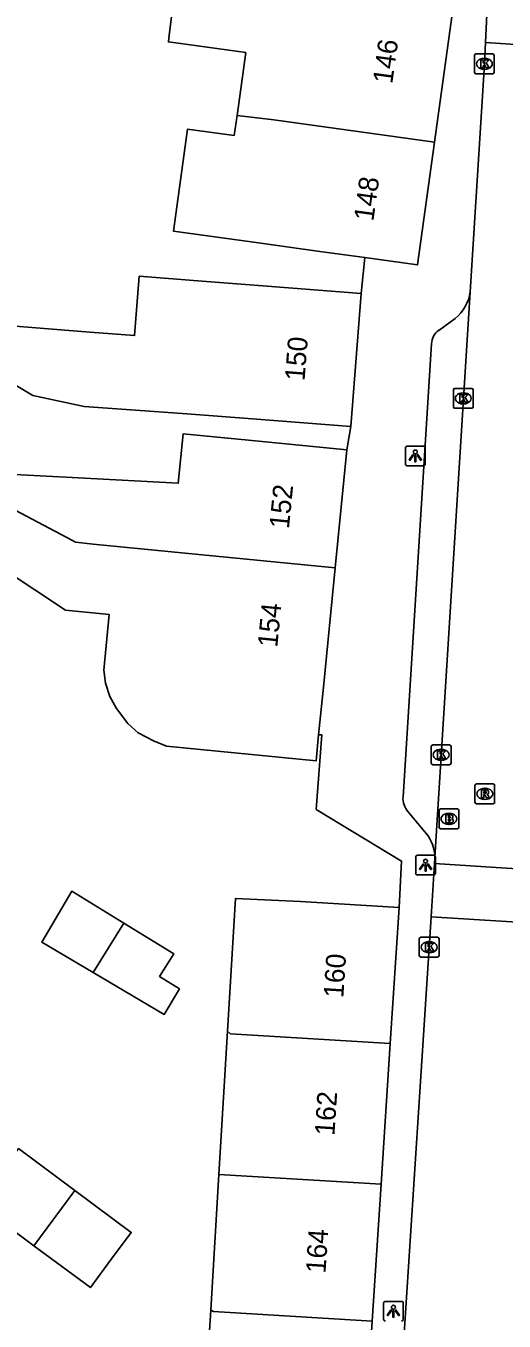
# Model space of a CAD drawing. Extents: x 160107 to 160928, y 382056 to 382918.
# Drawn here: x 160535.6 to 160559.8, y 382517.3 to 382582.9 of the extents above; entities that cross this region are included whole.
import ezdxf

# ---------------------------------------------------------------- set-up
doc = ezdxf.new("R2010")
doc.units = 0
for name, color, linetype in [('IMGEO_Brandkraan', 7, 'Continuous'), ('IMGEO_Kolk', 7, 'Continuous'), ('IMGEO_Lichtpunt', 7, 'Continuous'), ('IMGEO_Pand', 7, 'Continuous'), ('IMGEO_Pand_nummerreeks', 7, 'Continuous'), ('IMGEO_Rijbaan_lokaal_open', 7, 'Continuous'), ('IMGEO_Rioolput', 7, 'Continuous'), ('IMGEO_Voetpad_open', 7, 'Continuous')]:
    doc.layers.add(name, color=color, linetype=linetype)

msp = doc.modelspace()

# ---------------------------------------------------------------- linework, layer by layer
at = {"layer": 'IMGEO_Brandkraan'}
for p, q in [((160556.501, 382542.322), (160556.501, 382543.174)), ((160556.576, 382543.248), (160557.428, 382543.248)), ((160556.989, 382543.028), (160557.014, 382543.028)), ((160557.502, 382543.174), (160557.502, 382542.322)), ((160557.428, 382542.248), (160556.576, 382542.248)), ((160557.012, 382542.468), (160556.987, 382542.468))]:
    msp.add_line(p, q, dxfattribs=at)
for points in [[(160556.501, 382542.322), (160556.501, 382543.174)], [(160556.576, 382543.248), (160557.428, 382543.248)], [(160556.849, 382542.948), (160556.849, 382542.548), (160557.062, 382542.548)], [(160557.08, 382542.948), (160556.849, 382542.948)], [(160557.028, 382542.867), (160556.974, 382542.867), (160556.974, 382542.791)], [(160556.974, 382542.791), (160557.027, 382542.791)], [(160557.502, 382543.174), (160557.502, 382542.322)], [(160557.428, 382542.248), (160556.576, 382542.248)], [(160557.036, 382542.715), (160556.974, 382542.715), (160556.974, 382542.634)], [(160556.974, 382542.634), (160557.036, 382542.634)]]:
    msp.add_lwpolyline(points, dxfattribs=at)
for centre, radius, start, end in [((160556.578, 382543.172), 0.0765, 91.55205, 178.44795), ((160556.578, 382543.172), 0.0765, 91.55205, 178.44795), ((160557.029, 382542.829), 0.0379, 267.82845, 90.93552), ((160557.084, 382542.803), 0.145, 59.4692, 91.53667), ((160557.109, 382542.85), 0.0922, 285.51372, 58.15012), ((160557.114, 382542.658), 0.105, 301.31148, 78.98903), ((160557.426, 382543.172), 0.0765, 1.55205, 88.44795), ((160557.426, 382543.172), 0.0765, 1.55205, 88.44795), ((160556.578, 382542.324), 0.0765, 181.55205, 268.44795), ((160556.578, 382542.324), 0.0765, 181.55205, 268.44795), ((160557.037, 382542.674), 0.0404, 269.87594, 90.50774), ((160557.068, 382542.799), 0.251, 268.66757, 293.53466), ((160557.426, 382542.324), 0.0765, 271.55205, 358.44795), ((160557.426, 382542.324), 0.0765, 271.55205, 358.44795)]:
    msp.add_arc(centre, radius, start, end, dxfattribs=at)
for centre, major_axis, ratio, start_param, end_param in [((160556.988, 382542.748), (-0.387, 0.002), 0.722429, 4.712389, 7.853982), ((160557.013, 382542.748), (-0.39, 0.002), 0.717154, 1.570796, 4.712389)]:
    msp.add_ellipse(centre, major_axis=major_axis, ratio=ratio, start_param=start_param, end_param=end_param, dxfattribs=at)
at = {"layer": 'IMGEO_Kolk'}
for p, q in [((160558.369, 382581.452), (160559.221, 382581.452)), ((160558.294, 382580.526), (160558.294, 382581.378)), ((160558.782, 382581.232), (160558.807, 382581.232)), ((160559.295, 382581.378), (160559.295, 382580.526)), ((160559.221, 382580.452), (160558.369, 382580.452)), ((160558.805, 382580.672), (160558.78, 382580.672)), ((160557.225, 382563.598), (160557.225, 382564.45)), ((160557.3, 382564.524), (160558.152, 382564.524)), ((160558.226, 382564.45), (160558.226, 382563.598)), ((160557.736, 382563.744), (160557.711, 382563.744)), ((160557.713, 382564.304), (160557.738, 382564.304)), ((160558.152, 382563.524), (160557.3, 382563.524)), ((160556.105, 382545.563), (160556.105, 382546.415)), ((160556.18, 382546.489), (160557.032, 382546.489)), ((160556.593, 382546.269), (160556.618, 382546.269)), ((160557.106, 382546.415), (160557.106, 382545.563)), ((160557.032, 382545.489), (160556.18, 382545.489)), ((160556.616, 382545.709), (160556.591, 382545.709)), ((160555.498, 382535.827), (160555.498, 382536.679)), ((160555.573, 382536.753), (160556.425, 382536.753)), ((160555.986, 382536.533), (160556.011, 382536.533)), ((160556.499, 382536.679), (160556.499, 382535.827)), ((160556.425, 382535.753), (160555.573, 382535.753)), ((160556.009, 382535.973), (160555.984, 382535.973))]:
    msp.add_line(p, q, dxfattribs=at)
for points in [[(160558.369, 382581.452), (160559.221, 382581.452)], [(160558.294, 382580.526), (160558.294, 382581.378)], [(160558.615, 382581.152), (160558.738, 382581.152), (160558.738, 382581.001), (160558.868, 382581.152), (160559.032, 382581.152), (160558.886, 382581.001), (160559.039, 382580.752), (160558.887, 382580.752), (160558.802, 382580.916), (160558.738, 382580.849), (160558.738, 382580.752), (160558.615, 382580.752), (160558.615, 382581.152)], [(160559.295, 382581.378), (160559.295, 382580.526)], [(160559.221, 382580.452), (160558.369, 382580.452)], [(160557.225, 382563.598), (160557.225, 382564.45)], [(160557.3, 382564.524), (160558.152, 382564.524)], [(160558.226, 382564.45), (160558.226, 382563.598)], [(160557.546, 382564.224), (160557.669, 382564.224), (160557.669, 382564.073), (160557.799, 382564.224), (160557.963, 382564.224), (160557.817, 382564.073), (160557.97, 382563.824), (160557.818, 382563.824), (160557.733, 382563.988), (160557.669, 382563.921), (160557.669, 382563.824), (160557.546, 382563.824), (160557.546, 382564.224)], [(160558.152, 382563.524), (160557.3, 382563.524)], [(160556.105, 382545.563), (160556.105, 382546.415)], [(160556.18, 382546.489), (160557.032, 382546.489)], [(160556.426, 382546.189), (160556.549, 382546.189), (160556.549, 382546.038), (160556.679, 382546.189), (160556.843, 382546.189), (160556.697, 382546.038), (160556.85, 382545.789), (160556.698, 382545.789), (160556.613, 382545.953), (160556.549, 382545.886), (160556.549, 382545.789), (160556.426, 382545.789), (160556.426, 382546.189)], [(160557.106, 382546.415), (160557.106, 382545.563)], [(160557.032, 382545.489), (160556.18, 382545.489)], [(160555.498, 382535.827), (160555.498, 382536.679)], [(160555.573, 382536.753), (160556.425, 382536.753)], [(160555.819, 382536.453), (160555.942, 382536.453), (160555.942, 382536.302), (160556.072, 382536.453), (160556.236, 382536.453), (160556.09, 382536.302), (160556.243, 382536.053), (160556.091, 382536.053), (160556.006, 382536.217), (160555.942, 382536.15), (160555.942, 382536.053), (160555.819, 382536.053), (160555.819, 382536.453)], [(160556.499, 382536.679), (160556.499, 382535.827)], [(160556.425, 382535.753), (160555.573, 382535.753)]]:
    msp.add_lwpolyline(points, dxfattribs=at)
for centre, start, end in [((160558.371, 382581.376), 91.55205, 178.44795), ((160558.371, 382581.376), 91.55205, 178.44795), ((160559.219, 382581.376), 1.55205, 88.44795), ((160559.219, 382581.376), 1.55205, 88.44795), ((160558.371, 382580.528), 181.55205, 268.44795), ((160558.371, 382580.528), 181.55205, 268.44795), ((160559.219, 382580.528), 271.55205, 358.44795), ((160559.219, 382580.528), 271.55205, 358.44795), ((160557.302, 382564.448), 91.55205, 178.44795), ((160557.302, 382564.448), 91.55205, 178.44795), ((160558.15, 382564.448), 1.55205, 88.44795), ((160558.15, 382564.448), 1.55205, 88.44795), ((160557.302, 382563.6), 181.55205, 268.44795), ((160557.302, 382563.6), 181.55205, 268.44795), ((160558.15, 382563.6), 271.55205, 358.44795), ((160558.15, 382563.6), 271.55205, 358.44795), ((160556.182, 382546.413), 91.55205, 178.44795), ((160556.182, 382546.413), 91.55205, 178.44795), ((160557.03, 382546.413), 1.55205, 88.44795), ((160557.03, 382546.413), 1.55205, 88.44795), ((160556.182, 382545.565), 181.55205, 268.44795), ((160556.182, 382545.565), 181.55205, 268.44795), ((160557.03, 382545.565), 271.55205, 358.44795), ((160557.03, 382545.565), 271.55205, 358.44795), ((160555.575, 382536.677), 91.55205, 178.44795), ((160555.575, 382536.677), 91.55205, 178.44795), ((160556.423, 382536.677), 1.55205, 88.44795), ((160556.423, 382536.677), 1.55205, 88.44795), ((160555.575, 382535.829), 181.55205, 268.44795), ((160555.575, 382535.829), 181.55205, 268.44795), ((160556.423, 382535.829), 271.55205, 358.44795), ((160556.423, 382535.829), 271.55205, 358.44795)]:
    msp.add_arc(centre, 0.0765, start, end, dxfattribs=at)
for centre, major_axis, ratio, start_param, end_param in [((160558.781, 382580.952), (-0.387, 0.002), 0.722429, 4.712389, 7.853982), ((160558.806, 382580.952), (-0.39, 0.002), 0.717154, 1.570796, 4.712389), ((160557.712, 382564.024), (-0.387, 0.002), 0.722429, 4.712389, 7.853982), ((160557.737, 382564.024), (-0.39, 0.002), 0.717154, 1.570796, 4.712389), ((160556.592, 382545.989), (-0.387, 0.002), 0.722429, 4.712389, 7.853982), ((160556.617, 382545.989), (-0.39, 0.002), 0.717154, 1.570796, 4.712389), ((160555.985, 382536.253), (-0.387, 0.002), 0.722429, 4.712389, 7.853982), ((160556.01, 382536.253), (-0.39, 0.002), 0.717154, 1.570796, 4.712389)]:
    msp.add_ellipse(centre, major_axis=major_axis, ratio=ratio, start_param=start_param, end_param=end_param, dxfattribs=at)
at = {"layer": 'IMGEO_Lichtpunt'}
for p, q in [((160554.801, 382561.513), (160554.801, 382560.706)), ((160554.801, 382561.513), (160554.801, 382560.706)), ((160555.703, 382561.608), (160554.895, 382561.608)), ((160555.703, 382561.608), (160554.895, 382561.608)), ((160555.797, 382560.706), (160555.797, 382561.513)), ((160555.797, 382560.706), (160555.797, 382561.513)), ((160554.895, 382560.612), (160555.703, 382560.612)), ((160554.895, 382560.612), (160555.703, 382560.612)), ((160555.317, 382540.808), (160555.317, 382540.001)), ((160555.317, 382540.808), (160555.317, 382540.001)), ((160556.219, 382540.903), (160555.411, 382540.903)), ((160556.219, 382540.903), (160555.411, 382540.903)), ((160556.313, 382540.001), (160556.313, 382540.808)), ((160556.313, 382540.001), (160556.313, 382540.808)), ((160555.411, 382539.907), (160556.219, 382539.907)), ((160555.411, 382539.907), (160556.219, 382539.907)), ((160553.69, 382518.235), (160553.69, 382517.428)), ((160553.69, 382518.235), (160553.69, 382517.428)), ((160554.592, 382518.33), (160553.784, 382518.33)), ((160554.592, 382518.33), (160553.784, 382518.33)), ((160554.686, 382517.428), (160554.686, 382518.235)), ((160554.686, 382517.428), (160554.686, 382518.235))]:
    msp.add_line(p, q, dxfattribs=at)
for points in [[(160555.175, 382561.177), (160555.214, 382561.149), (160555.026, 382560.887), (160554.988, 382560.914), (160555.175, 382561.177)], [(160555.277, 382561.129), (160555.324, 382561.129), (160555.324, 382560.807), (160555.277, 382560.807), (160555.277, 382561.129)], [(160555.387, 382561.149), (160555.425, 382561.176), (160555.612, 382560.914), (160555.573, 382560.886), (160555.387, 382561.149)], [(160555.691, 382540.472), (160555.73, 382540.444), (160555.542, 382540.182), (160555.504, 382540.209), (160555.691, 382540.472)], [(160555.793, 382540.424), (160555.84, 382540.424), (160555.84, 382540.102), (160555.793, 382540.102), (160555.793, 382540.424)], [(160555.903, 382540.444), (160555.941, 382540.471), (160556.128, 382540.209), (160556.089, 382540.181), (160555.903, 382540.444)], [(160554.064, 382517.899), (160554.103, 382517.871), (160553.915, 382517.609), (160553.877, 382517.636), (160554.064, 382517.899)], [(160554.166, 382517.851), (160554.213, 382517.851), (160554.213, 382517.529), (160554.166, 382517.529), (160554.166, 382517.851)], [(160554.276, 382517.871), (160554.314, 382517.898), (160554.501, 382517.636), (160554.462, 382517.608), (160554.276, 382517.871)]]:
    msp.add_lwpolyline(points, dxfattribs=at)
for centre in [(160555.3, 382561.311), (160555.816, 382540.606), (160554.189, 382518.033)]:
    msp.add_circle(centre, 0.0994, dxfattribs=at)
for centre, start, end in [((160554.895, 382561.513), 90, 180), ((160554.895, 382561.513), 90, 180), ((160555.703, 382561.513), 0, 90), ((160555.703, 382561.513), 0, 90), ((160554.895, 382560.706), 180, 270), ((160554.895, 382560.706), 180, 270), ((160555.703, 382560.706), 270, 0), ((160555.703, 382560.706), 270, 360), ((160555.411, 382540.808), 90, 180), ((160555.411, 382540.808), 90, 180), ((160556.219, 382540.808), 0, 90), ((160556.219, 382540.808), 0, 90), ((160555.411, 382540.001), 180, 270), ((160555.411, 382540.001), 180, 270), ((160556.219, 382540.001), 270, 0), ((160556.219, 382540.001), 270, 360), ((160553.784, 382518.235), 90, 180), ((160553.784, 382518.235), 90, 180), ((160554.592, 382518.235), 0, 90), ((160554.592, 382518.235), 0, 90), ((160553.784, 382517.428), 180, 270), ((160553.784, 382517.428), 180, 270), ((160554.592, 382517.428), 270, 0), ((160554.592, 382517.428), 270, 360)]:
    msp.add_arc(centre, 0.0946, start, end, dxfattribs=at)
at = {"layer": 'IMGEO_Pand'}
for points in [[(160544.031, 382592.059), (160542.826, 382582.251), (160542.799, 382582.058), (160546.714, 382581.519), (160546.277, 382578.344)], [(160557.335, 382584.697), (160556.273, 382576.99)], [(160546.277, 382578.344), (160546.137, 382577.329), (160543.774, 382577.654), (160543.062, 382572.483), (160547.358, 382571.891), (160550.464, 382571.463), (160552.74, 382571.149)], [(160546.277, 382578.344), (160548.143, 382578.112), (160556.273, 382576.99)], [(160556.273, 382576.99), (160555.417, 382570.78), (160552.74, 382571.149)], [(160552.564, 382569.329), (160547.58, 382569.718), (160544.296, 382569.974), (160541.327, 382570.206), (160541.092, 382567.202), (160538.823, 382567.379), (160534.423, 382567.722), (160534.226, 382565.184), (160535.938, 382564.173), (160538.538, 382563.615), (160543.727, 382563.248), (160547.056, 382562.989), (160552.04, 382562.601)], [(160552.564, 382569.329), (160552.04, 382562.601)], [(160551.827, 382561.414), (160546.852, 382561.905), (160543.549, 382562.231), (160543.303, 382559.732), (160538.255, 382559.998), (160534.372, 382560.203), (160534.13, 382558.833)], [(160551.827, 382561.414), (160551.24, 382555.455)], [(160534.13, 382558.833), (160532.862, 382556.422), (160537.595, 382553.305), (160539.806, 382553.087), (160539.529, 382550.277), (160539.612, 382549.61), (160539.842, 382548.94), (160540.177, 382548.324), (160540.742, 382547.567), (160541.272, 382547.092), (160542.048, 382546.688), (160542.701, 382546.424), (160550.275, 382545.677), (160550.406, 382547)], [(160534.13, 382558.833), (160537.943, 382556.836), (160538.099, 382556.743), (160538.999, 382556.655), (160551.24, 382555.455)], [(160551.24, 382555.455), (160550.643, 382549.403), (160550.406, 382547)], [(160540.55, 382537.465), (160537.908, 382539.086), (160536.39, 382536.513), (160538.987, 382534.981)], [(160554.477, 382538.267), (160549.487, 382538.567), (160546.203, 382538.72), (160545.796, 382532)], [(160554.477, 382538.267), (160554.031, 382531.388)], [(160538.987, 382534.981), (160540.55, 382537.465)], [(160538.987, 382534.981), (160542.594, 382532.854), (160543.356, 382534.145), (160542.351, 382534.777), (160543.07, 382535.92), (160540.55, 382537.465)], [(160545.796, 382532), (160545.358, 382524.757)], [(160545.796, 382532), (160545.938, 382531.875), (160554.031, 382531.388)], [(160554.031, 382531.388), (160553.57, 382524.261)], [(160538.069, 382523.943), (160535.214, 382526.061), (160534.176, 382524.662), (160533.142, 382523.268), (160535.996, 382521.15)], [(160545.358, 382524.757), (160544.942, 382517.894)], [(160553.57, 382524.261), (160545.358, 382524.757)], [(160535.996, 382521.15), (160538.069, 382523.943)], [(160535.996, 382521.15), (160538.851, 382519.032), (160539.928, 382520.484), (160540.923, 382521.825), (160538.069, 382523.943)], [(160553.57, 382524.261), (160553.121, 382517.336)], [(160544.942, 382517.894), (160544.862, 382516.571), (160543.147, 382516.638), (160542.97, 382513.555), (160544.676, 382513.487), (160544.519, 382510.898), (160547.682, 382510.707), (160552.672, 382510.406)], [(160544.942, 382517.894), (160545.09, 382517.821), (160553.121, 382517.336)], [(160553.121, 382517.336), (160552.672, 382510.406)]]:
    msp.add_lwpolyline(points, dxfattribs=at)
at = {"layer": 'IMGEO_Rijbaan_lokaal_open'}
for points in [[(160558.845, 382582.037), (160559.2, 382589.486)], [(160558.072, 382569.42), (160558.793, 382580.934), (160558.845, 382582.037)], [(160564.68, 382581.638), (160558.845, 382582.037)], [(160556.291, 382540.798), (160558.072, 382569.42)], [(160556.271, 382540.489), (160556.291, 382540.798)], [(160556.099, 382537.796), (160556.271, 382540.489)], [(160556.271, 382540.489), (160562.258, 382540.108)], [(160554.615, 382514.878), (160555.566, 382529.462), (160556.099, 382537.796)], [(160562.086, 382537.415), (160556.099, 382537.796)]]:
    msp.add_lwpolyline(points, dxfattribs=at)
at = {"layer": 'IMGEO_Rioolput'}
for p, q in [((160558.314, 382543.586), (160558.314, 382544.438)), ((160558.389, 382544.512), (160559.241, 382544.512)), ((160558.802, 382544.292), (160558.827, 382544.292)), ((160559.315, 382544.438), (160559.315, 382543.586)), ((160559.241, 382543.512), (160558.389, 382543.512)), ((160558.825, 382543.732), (160558.8, 382543.732))]:
    msp.add_line(p, q, dxfattribs=at)
for points in [[(160558.314, 382543.586), (160558.314, 382544.438)], [(160558.389, 382544.512), (160559.241, 382544.512)], [(160558.903, 382544.21), (160558.651, 382544.212), (160558.651, 382543.812)], [(160558.829, 382544.131), (160558.775, 382544.131), (160558.775, 382544.05)], [(160559.315, 382544.438), (160559.315, 382543.586)], [(160559.241, 382543.512), (160558.389, 382543.512)], [(160558.651, 382543.812), (160558.775, 382543.812), (160558.775, 382543.974), (160558.786, 382543.974)], [(160558.775, 382544.05), (160558.827, 382544.05)], [(160558.833, 382543.945), (160558.904, 382543.812), (160559.044, 382543.812), (160558.979, 382543.938)]]:
    msp.add_lwpolyline(points, dxfattribs=at)
for centre, radius, start, end in [((160558.391, 382544.436), 0.0765, 91.55205, 178.44795), ((160558.391, 382544.436), 0.0765, 91.55205, 178.44795), ((160558.835, 382544.035), 0.0964, 77.00612, 93.18647), ((160558.849, 382544.092), 0.0378, 276.66336, 79.67722), ((160558.902, 382544.1), 0.109, 350.36119, 89.41601), ((160558.9, 382544.1), 0.112, 277.58423, 350.98172), ((160559.239, 382544.436), 0.0765, 1.55205, 88.44795), ((160559.239, 382544.436), 0.0765, 1.55205, 88.44795), ((160558.391, 382543.588), 0.0765, 181.55205, 268.44795), ((160558.391, 382543.588), 0.0765, 181.55205, 268.44795), ((160558.785, 382543.921), 0.0533, 26.02933, 88.69889), ((160558.811, 382544.239), 0.19, 274.7715, 282.96867), ((160558.884, 382543.885), 0.108, 29.51342, 73.79051), ((160559.239, 382543.588), 0.0765, 271.55205, 358.44795), ((160559.239, 382543.588), 0.0765, 271.55205, 358.44795)]:
    msp.add_arc(centre, radius, start, end, dxfattribs=at)
for centre, major_axis, ratio, start_param, end_param in [((160558.801, 382544.012), (-0.387, 0.002), 0.722429, 4.712389, 7.853982), ((160558.826, 382544.012), (-0.39, 0.002), 0.717154, 1.570796, 4.712389)]:
    msp.add_ellipse(centre, major_axis=major_axis, ratio=ratio, start_param=start_param, end_param=end_param, dxfattribs=at)
at = {"layer": 'IMGEO_Voetpad_open'}
for points in [[(160552.74, 382571.149), (160552.564, 382569.329)], [(160556.487, 382567.467), (160557.316, 382568.071)], [(160554.676, 382543.869), (160556.116, 382566.791)], [(160552.04, 382562.601), (160551.827, 382561.414)], [(160550.406, 382547), (160550.574, 382546.994), (160550.277, 382543.226), (160554.602, 382540.614), (160554.477, 382538.267)], [(160555.849, 382542.013), (160554.93, 382543.102)]]:
    msp.add_lwpolyline(points, dxfattribs=at)
for centre, radius, start, end in [((160556.05, 382569.667), 2.037, 308.42621, 353.03993), ((160557.018, 382566.736), 0.904, 125.98118, 176.50141), ((160555.76, 382543.802), 1.086, 176.48025, 220.1654), ((160554.275, 382540.753), 2.016, 1.28836, 38.693)]:
    msp.add_arc(centre, radius, start, end, dxfattribs=at)

# ---------------------------------------------------------------- texts
at = {"layer": 'IMGEO_Pand_nummerreeks'}
for s, rotation, p in [('146', 82.15642, (160554.131, 382579.912)), ('148', 82.15168, (160553.174, 382572.958)), ('150', 85.54659, (160549.69, 382564.881)), ('152', 84.37376, (160548.899, 382557.398)), ('154', 84.36804, (160548.308, 382551.395)), ('160', 86.29322, (160551.653, 382533.667)), ('162', 86.29322, (160551.202, 382526.696)), ('164', 86.29322, (160550.751, 382519.732))]:
    msp.add_text(s, height=1, rotation=rotation, dxfattribs=at).set_placement(p)

doc.saveas('drawing.dxf')
